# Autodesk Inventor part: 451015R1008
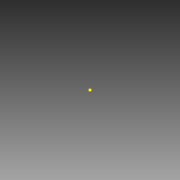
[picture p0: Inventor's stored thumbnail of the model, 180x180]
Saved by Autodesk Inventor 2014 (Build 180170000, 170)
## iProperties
Created: 2015-10
Part Number: 451015R1008
Material: Generic
Document SubType Name: Modeling
Designer: youjin21
Density: 1 g/cm^3
Appearance: Default
Author: youjin21
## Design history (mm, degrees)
sketch "Sketch1"
  geometry: 1 further point
  constraints: 1 other
